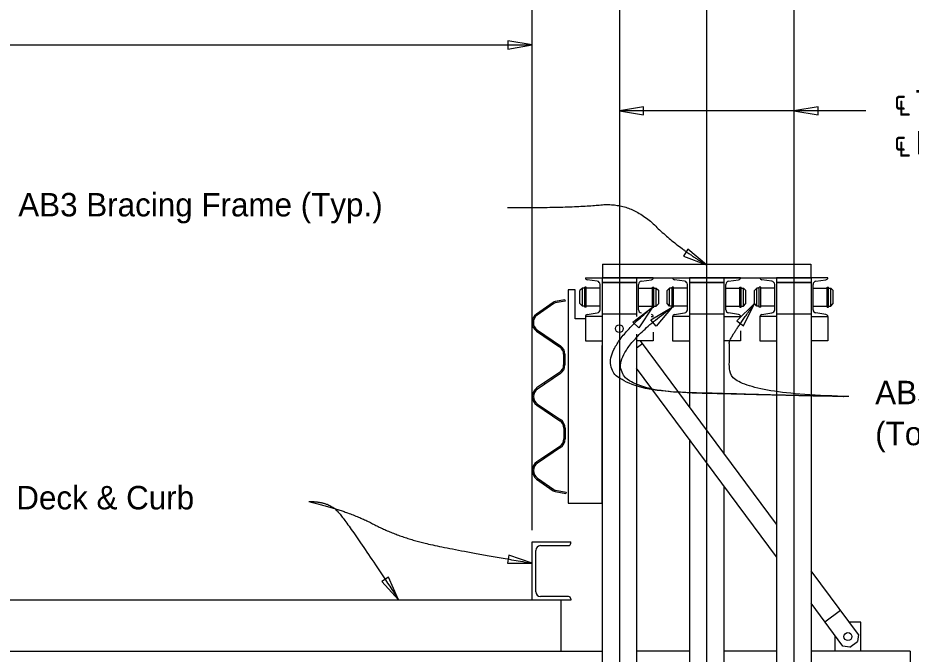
# Model space of a CAD drawing. Extents: x 11137.4 to 11208.2, y 76297.7 to 76332.4.
# Drawn here: x 11164.53 to 11172.2, y 76320.94 to 76326.4 of the extents above; entities that cross this region are included whole.
import ezdxf

# ---------------------------------------------------------------- set-up
doc = ezdxf.new("R2010")
doc.units = 0
for name, color, linetype in [('CL_Minor', 7, 'Continuous'), ('Dimension', 7, 'Continuous'), ('Miscellaneous', 7, 'Continuous'), ('SteelMisc', 7, 'Continuous'), ('TextStructures', 7, 'Continuous'), ('Wood', 7, 'Continuous')]:
    doc.layers.add(name, color=color, linetype=linetype)

msp = doc.modelspace()

# ---------------------------------------------------------------- linework, layer by layer
at = {"layer": 'CL_Minor'}
for p, q in [((11171.1956, 76329.4016), (11171.1956, 76316.9297)), ((11169.6957, 76328.3721), (11169.6957, 76316.9297)), ((11170.4457, 76328.3721), (11170.4457, 76316.9297))]:
    msp.add_line(p, q, dxfattribs=at)
at = {"layer": 'Dimension'}
for p, q in [((11168.9456, 76322.0004), (11168.9456, 76327.4238)), ((11144.9456, 76326.1708), (11168.9456, 76326.1708)), ((11171.8153, 76325.6047), (11169.6957, 76325.6047))]:
    msp.add_line(p, q, dxfattribs=at)
for points in [[(11168.7374, 76326.1355), (11168.9456, 76326.1708), (11168.7374, 76326.2061)], [(11169.6957, 76325.6047), (11169.9039, 76325.5694), (11169.9039, 76325.6399)], [(11171.1956, 76325.6047), (11171.4038, 76325.5694), (11171.4038, 76325.6399)], [(11170.4457, 76324.2808), (11170.284, 76324.4168), (11170.2483, 76324.356)], [(11169.8126, 76323.789), (11169.9807, 76323.9167), (11169.864, 76323.7407)], [(11169.9675, 76323.8081), (11170.1487, 76323.9167), (11170.0134, 76323.7545)], [(11170.8571, 76323.9475), (11170.7062, 76323.7997), (11170.7633, 76323.7583)], [(11168.9458, 76321.7175), (11168.7463, 76321.787), (11168.7346, 76321.7175)], [(11167.798, 76321.404), (11167.7133, 76321.5976), (11167.6543, 76321.5589)]]:
    msp.add_lwpolyline(points, close=True, dxfattribs=at)
for points in [[(11168.7336, 76324.7727), (11169.2761, 76324.7715), (11169.7946, 76324.821), (11170.1997, 76324.4255), (11170.4457, 76324.2808)], [(11171.6681, 76323.1492), (11171.4679, 76323.1492), (11169.1261, 76323.2162), (11169.9807, 76323.9167)], [(11171.6681, 76323.1492), (11171.4679, 76323.1492), (11169.1839, 76323.2104), (11170.1487, 76323.9167)], [(11171.6681, 76323.1492), (11170.6437, 76323.174), (11170.6409, 76323.5811), (11170.6409, 76323.6496), (11170.8571, 76323.9475)], [(11167.0263, 76322.248), (11167.1855, 76322.248), (11167.3398, 76322.1033), (11167.798, 76321.404)], [(11167.0263, 76322.248), (11167.3687, 76322.166), (11167.7883, 76321.9442), (11168.2899, 76321.8284), (11168.9458, 76321.7175)]]:
    msp.add_open_spline(points, degree=2, dxfattribs=at)
at = {"layer": 'Miscellaneous'}
for p, q in [((11168.9456, 76321.3996), (11168.9456, 76321.8996)), ((11168.9456, 76321.8996), (11169.2789, 76321.8996)), ((11169.2789, 76321.8892), (11169.2789, 76321.8996)), ((11168.9768, 76321.4725), (11168.9768, 76321.8267)), ((11169.0185, 76321.8684), (11169.2581, 76321.8684)), ((11168.9456, 76321.3996), (11144.9456, 76321.3996)), ((11169.2789, 76321.3996), (11168.9456, 76321.3996)), ((11169.2581, 76321.4308), (11169.0185, 76321.4308)), ((11169.1956, 76320.9621), (11169.1956, 76321.3996)), ((11169.2789, 76321.41), (11169.2789, 76321.3996))]:
    msp.add_line(p, q, dxfattribs=at)
for centre, radius, start, end in [((11169.0185, 76321.8267), 0.0417, 90.00028, 180), ((11169.2581, 76321.8892), 0.0208, 270, 360), ((11169.0185, 76321.4725), 0.0417, 180, 269.99972), ((11169.2581, 76321.41), 0.0208, 0, 90)]:
    msp.add_arc(centre, radius, start, end, dxfattribs=at)
at = {"layer": 'SteelMisc'}
for p, q in [((11169.5497, 76324.2879), (11171.3414, 76324.2879)), ((11169.5497, 76324.2879), (11169.5497, 76324.1704)), ((11171.3414, 76324.2879), (11171.3414, 76324.1704)), ((11169.4039, 76324.1704), (11169.5474, 76324.1704)), ((11169.5062, 76324.1398), (11169.4205, 76324.1524)), ((11169.8438, 76324.1704), (11169.5474, 76324.1704)), ((11169.5474, 76324.1704), (11169.5474, 76323.8371)), ((11169.8438, 76324.1287), (11169.5474, 76324.1287)), ((11169.5474, 76324.1287), (11169.8438, 76324.1287)), ((11169.5497, 76324.1704), (11171.3414, 76324.1704)), ((11169.9872, 76324.1704), (11169.8438, 76324.1704)), ((11169.8438, 76324.1704), (11169.8438, 76323.8371)), ((11169.885, 76324.1398), (11169.9707, 76324.1524)), ((11170.1539, 76324.1704), (11170.2974, 76324.1704)), ((11170.2562, 76324.1398), (11170.1705, 76324.1524)), ((11170.2974, 76324.1704), (11170.2974, 76323.8371)), ((11170.5938, 76324.1704), (11170.2974, 76324.1704)), ((11170.5938, 76324.1287), (11170.2974, 76324.1287)), ((11170.2974, 76324.1287), (11170.5938, 76324.1287)), ((11170.7372, 76324.1704), (11170.5938, 76324.1704)), ((11170.5938, 76324.1704), (11170.5938, 76323.8371)), ((11170.635, 76324.1398), (11170.7207, 76324.1524)), ((11170.9039, 76324.1704), (11171.0474, 76324.1704)), ((11171.0062, 76324.1398), (11170.9205, 76324.1524)), ((11171.3438, 76324.1704), (11171.0474, 76324.1704)), ((11171.0474, 76324.1704), (11171.0474, 76323.8371)), ((11171.3438, 76324.1287), (11171.0474, 76324.1287)), ((11171.0474, 76324.1287), (11171.3438, 76324.1287)), ((11171.4872, 76324.1704), (11171.3438, 76324.1704)), ((11171.3438, 76324.1704), (11171.3438, 76323.8371)), ((11171.385, 76324.1398), (11171.4707, 76324.1524)), ((11169.3779, 76324.0807), (11169.3571, 76324.0599)), ((11169.3571, 76323.9475), (11169.3571, 76324.0599)), ((11169.3779, 76323.9267), (11169.3779, 76324.0807)), ((11169.3987, 76324.0807), (11169.3779, 76324.0807)), ((11169.3987, 76323.9167), (11169.3987, 76324.0907)), ((11169.4104, 76324.0907), (11169.3987, 76324.0907)), ((11169.4104, 76323.9167), (11169.4104, 76324.0907)), ((11169.5307, 76324.0807), (11169.4104, 76324.0807)), ((11169.5307, 76323.8944), (11169.5307, 76324.1131)), ((11169.8605, 76323.8944), (11169.8605, 76324.1131)), ((11169.8605, 76324.0807), (11169.9807, 76324.0807)), ((11169.9807, 76324.0907), (11169.9925, 76324.0907)), ((11169.9807, 76323.9167), (11169.9807, 76324.0907)), ((11169.9925, 76323.9167), (11169.9925, 76324.0907)), ((11169.9925, 76324.0807), (11170.0133, 76324.0807)), ((11170.0133, 76323.9267), (11170.0133, 76324.0807)), ((11170.0133, 76324.0807), (11170.0341, 76324.0599)), ((11170.0341, 76323.9475), (11170.0341, 76324.0599)), ((11170.1279, 76324.0807), (11170.1071, 76324.0599)), ((11170.1071, 76323.9475), (11170.1071, 76324.0599)), ((11170.1279, 76323.9267), (11170.1279, 76324.0807)), ((11170.1487, 76324.0807), (11170.1279, 76324.0807)), ((11170.1487, 76323.9167), (11170.1487, 76324.0907)), ((11170.1604, 76324.0907), (11170.1487, 76324.0907)), ((11170.1604, 76323.9167), (11170.1604, 76324.0907)), ((11170.2807, 76324.0807), (11170.1604, 76324.0807)), ((11170.2807, 76323.8944), (11170.2807, 76324.1131)), ((11170.6105, 76323.8944), (11170.6105, 76324.1131)), ((11170.6105, 76324.0807), (11170.7307, 76324.0807)), ((11170.7307, 76324.0907), (11170.7425, 76324.0907)), ((11170.7307, 76323.9167), (11170.7307, 76324.0907)), ((11170.7425, 76323.9167), (11170.7425, 76324.0907)), ((11170.7425, 76324.0807), (11170.7633, 76324.0807)), ((11170.7633, 76323.9267), (11170.7633, 76324.0807)), ((11170.7633, 76324.0807), (11170.7841, 76324.0599)), ((11170.7841, 76323.9475), (11170.7841, 76324.0599)), ((11170.8779, 76324.0807), (11170.8571, 76324.0599)), ((11170.8571, 76323.9475), (11170.8571, 76324.0599)), ((11170.8779, 76323.9267), (11170.8779, 76324.0807)), ((11170.8987, 76324.0807), (11170.8779, 76324.0807)), ((11170.8987, 76323.9167), (11170.8987, 76324.0907)), ((11170.9104, 76324.0907), (11170.8987, 76324.0907)), ((11170.9104, 76323.9167), (11170.9104, 76324.0907)), ((11171.0307, 76324.0807), (11170.9104, 76324.0807)), ((11171.0307, 76323.8944), (11171.0307, 76324.1131)), ((11171.3605, 76323.8944), (11171.3605, 76324.1131)), ((11171.3605, 76324.0807), (11171.4807, 76324.0807)), ((11171.4807, 76324.0907), (11171.4925, 76324.0907)), ((11171.4807, 76323.9167), (11171.4807, 76324.0907)), ((11171.4925, 76323.9167), (11171.4925, 76324.0907)), ((11171.4925, 76324.0807), (11171.5133, 76324.0807)), ((11171.5133, 76323.9267), (11171.5133, 76324.0807)), ((11171.5133, 76324.0807), (11171.5341, 76324.0599)), ((11171.5341, 76323.9475), (11171.5341, 76324.0599)), ((11169.2277, 76323.9799), (11169.1435, 76323.9651)), ((11169.2295, 76323.9689), (11169.1454, 76323.9541)), ((11169.2277, 76323.9799), (11169.2295, 76323.9689)), ((11169.1265, 76323.9581), (11168.9837, 76323.8582)), ((11169.1329, 76323.9489), (11168.9901, 76323.8491)), ((11169.0562, 76323.8953), (11169.0498, 76323.9044)), ((11169.1181, 76323.9387), (11169.1117, 76323.9477)), ((11169.3779, 76323.9267), (11169.3571, 76323.9475)), ((11169.3987, 76323.9267), (11169.3779, 76323.9267)), ((11169.4104, 76323.9167), (11169.3987, 76323.9167)), ((11169.5307, 76323.9267), (11169.4104, 76323.9267)), ((11169.8605, 76323.9267), (11169.9807, 76323.9267)), ((11169.9807, 76323.9167), (11169.9925, 76323.9167)), ((11169.9925, 76323.9267), (11170.0133, 76323.9267)), ((11170.0133, 76323.9267), (11170.0341, 76323.9475)), ((11170.1279, 76323.9267), (11170.1071, 76323.9475)), ((11170.1487, 76323.9267), (11170.1279, 76323.9267)), ((11170.1604, 76323.9167), (11170.1487, 76323.9167)), ((11170.2807, 76323.9267), (11170.1604, 76323.9267)), ((11170.6105, 76323.9267), (11170.7307, 76323.9267)), ((11170.7307, 76323.9167), (11170.7425, 76323.9167)), ((11170.7425, 76323.9267), (11170.7633, 76323.9267)), ((11170.7633, 76323.9267), (11170.7841, 76323.9475)), ((11170.8779, 76323.9267), (11170.8571, 76323.9475)), ((11170.8987, 76323.9267), (11170.8779, 76323.9267)), ((11170.9104, 76323.9167), (11170.8987, 76323.9167)), ((11171.0307, 76323.9267), (11170.9104, 76323.9267)), ((11171.3605, 76323.9267), (11171.4807, 76323.9267)), ((11171.4807, 76323.9167), (11171.4925, 76323.9167)), ((11171.4925, 76323.9267), (11171.5133, 76323.9267)), ((11171.5133, 76323.9267), (11171.5341, 76323.9475)), ((11169.5474, 76323.8371), (11169.4039, 76323.8371)), ((11169.4039, 76323.8371), (11169.4039, 76323.6288)), ((11169.4205, 76323.8551), (11169.5062, 76323.8677)), ((11169.5474, 76323.8611), (11169.8438, 76323.8611)), ((11169.5474, 76323.8371), (11169.5474, 76319.423)), ((11169.8438, 76323.8371), (11169.8438, 76323.8371)), ((11169.885, 76323.8677), (11169.885, 76323.8677)), ((11169.9705, 76323.8371), (11169.9872, 76323.8371)), ((11169.9707, 76323.8551), (11169.9707, 76323.8551)), ((11170.2974, 76323.8371), (11170.1539, 76323.8371)), ((11170.1539, 76323.8371), (11170.1539, 76323.6288)), ((11170.1705, 76323.8551), (11170.2562, 76323.8677)), ((11170.2974, 76323.8611), (11170.5938, 76323.8611)), ((11170.2974, 76323.8371), (11170.2974, 76323.062)), ((11170.5938, 76323.8371), (11170.5938, 76322.6627)), ((11170.5938, 76323.8371), (11170.7372, 76323.8371)), ((11170.7207, 76323.8551), (11170.635, 76323.8677)), ((11170.7372, 76323.8371), (11170.7372, 76323.8371)), ((11171.0474, 76323.8371), (11170.9039, 76323.8371)), ((11170.9039, 76323.8371), (11170.9039, 76323.6288)), ((11170.9205, 76323.8551), (11171.0062, 76323.8677)), ((11171.0474, 76323.8611), (11171.3438, 76323.8611)), ((11171.0474, 76323.8371), (11171.0474, 76319.423)), ((11171.3438, 76323.8371), (11171.4872, 76323.8371)), ((11171.3438, 76323.8371), (11171.3438, 76319.423)), ((11171.4707, 76323.8551), (11171.385, 76323.8677)), ((11171.4872, 76323.8371), (11171.4872, 76323.6288)), ((11168.9849, 76323.7109), (11169.1826, 76323.5772)), ((11168.9912, 76323.7201), (11169.1889, 76323.5865)), ((11169.0558, 76323.6765), (11169.0495, 76323.6672)), ((11169.8438, 76323.6848), (11169.8438, 76319.423)), ((11169.9872, 76323.7037), (11169.9872, 76323.6288)), ((11170.7372, 76323.7152), (11170.7372, 76323.6288)), ((11169.1185, 76323.6342), (11169.1122, 76323.6249)), ((11169.4039, 76323.6288), (11169.5474, 76323.6288)), ((11169.9872, 76323.6288), (11169.8438, 76323.6288)), ((11169.8438, 76323.5691), (11169.8936, 76323.606)), ((11171.0474, 76322.0517), (11169.8766, 76323.6288)), ((11170.1539, 76323.6288), (11170.2974, 76323.6288)), ((11170.7372, 76323.6288), (11170.5938, 76323.6288)), ((11170.9039, 76323.6288), (11171.0474, 76323.6288)), ((11171.4872, 76323.6288), (11171.3438, 76323.6288)), ((11169.2168, 76323.5129), (11169.2168, 76323.4208)), ((11169.228, 76323.5129), (11169.228, 76323.4208)), ((11169.2168, 76323.4984), (11169.228, 76323.4984)), ((11169.2168, 76323.4359), (11169.228, 76323.4359)), ((11169.1826, 76323.3565), (11168.9849, 76323.2229)), ((11171.0474, 76321.7722), (11169.8438, 76323.3935)), ((11169.1889, 76323.3472), (11168.9912, 76323.2136)), ((11169.1185, 76323.2996), (11169.1122, 76323.3089)), ((11169.0558, 76323.2572), (11169.0495, 76323.2665)), ((11168.986, 76323.0755), (11169.1837, 76322.9419)), ((11168.9923, 76323.0848), (11169.1899, 76322.9511)), ((11169.0568, 76323.0411), (11169.0506, 76323.0319)), ((11169.1195, 76322.9989), (11169.1132, 76322.9895)), ((11169.2178, 76322.8775), (11169.2178, 76322.7854)), ((11169.2178, 76322.863), (11169.2291, 76322.863)), ((11169.229, 76322.8775), (11169.229, 76322.7854)), ((11169.2178, 76322.8005), (11169.2291, 76322.8005)), ((11170.2974, 76322.7825), (11170.2974, 76319.423)), ((11169.1837, 76322.7211), (11168.9861, 76322.5875)), ((11169.19, 76322.7118), (11168.9923, 76322.5782)), ((11169.1195, 76322.6641), (11169.1133, 76322.6735)), ((11169.0568, 76322.6219), (11169.0506, 76322.6311)), ((11168.9848, 76322.4403), (11169.1275, 76322.3403)), ((11168.9912, 76322.4494), (11169.134, 76322.3495)), ((11169.0573, 76322.4032), (11169.0509, 76322.394)), ((11169.1192, 76322.3598), (11169.1128, 76322.3507)), ((11170.5938, 76322.3832), (11170.5938, 76319.423)), ((11169.1445, 76322.3333), (11169.236, 76322.3171)), ((11169.1465, 76322.3443), (11169.2379, 76322.3282)), ((11169.2379, 76322.3282), (11169.236, 76322.3171)), ((11171.7514, 76321.1033), (11171.3438, 76321.6524)), ((11171.6175, 76321.0042), (11171.3438, 76321.3729)), ((11171.4618, 76321.214), (11171.5955, 76321.3133)), ((11171.7707, 76321.2121), (11171.6707, 76321.2121)), ((11171.7707, 76320.9621), (11171.7707, 76321.2121)), ((11171.5487, 76321.0969), (11171.5487, 76320.9621)), ((11171.7514, 76321.1033), (11171.7427, 76321.0449)), ((11171.676, 76320.9954), (11171.6175, 76321.0042)), ((11171.676, 76320.9954), (11171.7427, 76321.0449)), ((11144.3439, 76320.9621), (11169.5474, 76320.9621)), ((11170.2974, 76320.9621), (11169.8438, 76320.9621)), ((11171.0474, 76320.9621), (11170.5938, 76320.9621)), ((11172.1956, 76320.9621), (11171.3438, 76320.9621)), ((11172.1956, 76320.9621), (11172.1956, 76319.7954))]:
    msp.add_line(p, q, dxfattribs=at)
for centre in [(11169.6956, 76323.7329), (11171.6597, 76321.0871)]:
    msp.add_circle(centre, 0.0339, dxfattribs=at)
for centre, radius, start, end in [((11169.1391, 76323.5129), 0.0888, 360, 55.94528), ((11169.1391, 76323.5129), 0.0777, 360, 55.94528), ((11169.1391, 76323.4208), 0.0777, 304.05472, 360), ((11169.1391, 76323.4208), 0.0888, 304.05472, 360), ((11169.1402, 76322.8775), 0.0777, 0, 55.93934), ((11169.1402, 76322.8775), 0.0888, 0, 55.93934), ((11169.1402, 76322.7854), 0.0777, 304.06066, 359.99971), ((11169.1402, 76322.7854), 0.0888, 304.06066, 359.99971)]:
    msp.add_arc(centre, radius, start, end, dxfattribs=at)
for centre, major_axis, ratio, start_param, end_param in [((11169.4237, 76324.1704), (-0.0198, 0), 0.920395, 0, 1.40499), ((11169.5013, 76324.1131), (0.0294, 0), 0.920395, 0, 1.40499), ((11169.8899, 76324.1131), (-0.0294, 0), 0.920395, 4.878195, 6.283185), ((11169.9674, 76324.1704), (0.0198, 0), 0.920395, 4.878195, 6.283185), ((11170.1737, 76324.1704), (-0.0198, 0), 0.920395, 0, 1.40499), ((11170.2513, 76324.1131), (0.0294, 0), 0.920395, 0, 1.40499), ((11170.6399, 76324.1131), (-0.0294, 0), 0.920395, 4.878195, 6.283185), ((11170.7174, 76324.1704), (0.0198, 0), 0.920395, 4.878195, 6.283185), ((11170.9237, 76324.1704), (-0.0198, 0), 0.920395, 0, 1.40499), ((11171.0013, 76324.1131), (0.0294, 0), 0.920395, 0, 1.40499), ((11171.3899, 76324.1131), (-0.0294, 0), 0.920395, 4.878195, 6.283185), ((11171.4674, 76324.1704), (0.0198, 0), 0.920395, 4.878195, 6.283185), ((11169.1508, 76323.9233), (0, 0.0425), 0.999998, 0.174592, 0.610846), ((11169.1508, 76323.9233), (0, 0.0313), 0.999998, 0.174592, 0.610846), ((11169.5013, 76323.8944), (0.0294, 0), 0.920395, 4.878195, 6.283185), ((11169.8899, 76323.8944), (-0.0294, 0), 0.920395, 6.283185, 7.688175), ((11170.2513, 76323.8944), (0.0294, 0), 0.920395, 4.878195, 6.283185), ((11170.6399, 76323.8944), (-0.0294, 0), 0.920395, 6.283185, 7.688175), ((11171.0013, 76323.8944), (0.0294, 0), 0.920395, 4.878195, 6.283185), ((11171.3899, 76323.8944), (-0.0294, 0), 0.920395, 6.283185, 7.688175), ((11169.035, 76323.7849), (0, 0.0894), 0.999998, 0.610874, 2.5472), ((11169.035, 76323.7849), (0, 0.0782), 0.999998, 0.610874, 2.5472), ((11169.4237, 76323.8371), (-0.0198, 0), 0.920395, 4.878195, 6.283185), ((11169.9674, 76323.8371), (0.0198, 0), 0.920395, 0, 1.40499), ((11170.1737, 76323.8371), (-0.0198, 0), 0.920395, 4.878195, 6.283185), ((11170.7174, 76323.8371), (0.0198, 0), 0.920395, 0, 1.40499), ((11170.7174, 76323.8371), (0.0198, 0), 0.920395, 0, 6.864014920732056e-10), ((11170.9237, 76323.8371), (-0.0198, 0), 0.920395, 4.878195, 6.283185), ((11171.4674, 76323.8371), (0.0198, 0), 0.920395, 0, 1.40499), ((11169.0361, 76323.1495), (0, 0.0894), 0.999998, 0.610874, 2.5472), ((11169.0361, 76323.1495), (0, 0.0782), 0.999998, 0.610874, 2.5472), ((11169.0361, 76322.5134), (0, 0.0894), 0.999998, 0.594393, 2.530718), ((11169.0361, 76322.5134), (0, 0.0782), 0.999998, 0.594393, 2.530718), ((11169.1519, 76322.3751), (0, -0.0425), 0.999998, 5.67234, 6.108593), ((11169.1519, 76322.3751), (0, -0.0313), 0.999998, 5.67234, 6.108593)]:
    msp.add_ellipse(centre, major_axis=major_axis, ratio=ratio, start_param=start_param, end_param=end_param, dxfattribs=at)
at = {"layer": 'Wood'}
msp.add_lwpolyline([(11169.4039, 76323.8162), (11169.3154, 76323.8162), (11169.3154, 76324.0662), (11169.2557, 76324.0662), (11169.2557, 76322.2329), (11169.5474, 76322.2329), (11169.5474, 76323.5871)], dxfattribs=at)

# ---------------------------------------------------------------- texts
at = {"layer": 'Dimension'}
for s, p in [('℄ Trusses & ', (11172.0565, 76325.5822)), ('℄ Bearings ', (11172.0565, 76325.2301))]:
    msp.add_text(s, height=0.2016, dxfattribs=at).set_placement(p)
at = {"layer": 'TextStructures'}
for s, p in [('AB3 Bracing Frame (Typ.)', (11164.5305, 76324.6973)), ('AB51 Panel Pins ', (11171.8946, 76323.0832)), ('(Top & Bottom Typ.)', (11171.8946, 76322.7312)), ('Steel Grid Deck & Curb', (11163.2399, 76322.1798))]:
    msp.add_text(s, height=0.2016, dxfattribs=at).set_placement(p)

doc.saveas('drawing.dxf')
